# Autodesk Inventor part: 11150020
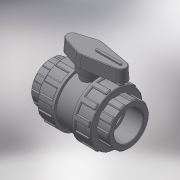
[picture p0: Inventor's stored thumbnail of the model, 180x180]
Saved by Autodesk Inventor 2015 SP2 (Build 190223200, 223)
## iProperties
Created: 2017-11
Part Number: 11150020
Material: Generic
Description: PLASSON 2/NUT VALVE CEM. PVC 20
Document SubType Name: Modeling
Designer: KIM
Density: 1 g/cm^3
Appearance: Default
Author: KIM
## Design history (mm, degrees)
derived "111500.ipt"
feature "Solid1::111500.ipt"
tag "TaggingFeature1"
body "Solid1"
other parameters: "d0" = 75, "d2" = 45, "d3" = 16, "d4" = 16, "d5" = 11.2, "d7" = 28, "d8" = 40.5, "d13" = 0.6, "d23" = 16, "d24" = 43.2, "d25" = 0.4, "d26" = 0.6, "d27" = 6.75, "d28" = 3.375, "d29" = 12, "d30" = 0, "d35" = 0.6, "d39" = 22.5, "d45" = 360 deg, "d47" = 0.4, "d50" = 24.75, "d51" = 13.5, "d53" = 0, "d55" = 4, "d56" = 2, "d57" = 11.2, "d58" = 0, "d59" = 0.6, "d61" = 360 deg, "d63" = 18, "d64" = 45, "d66" = 65, "d68" = 9, "d69" = 19.5, "d70" = 11.25, "d71" = 3 deg, "d73" = 0.9, "d74" = 26, "d75" = 1.35, "d76" = 0, "d77" = 0.4, "l_" = 16, "H_" = 75, "K_" = 45, "F_" = 45, "J_" = 65, "d67" = 18, "d72" = 4.5
